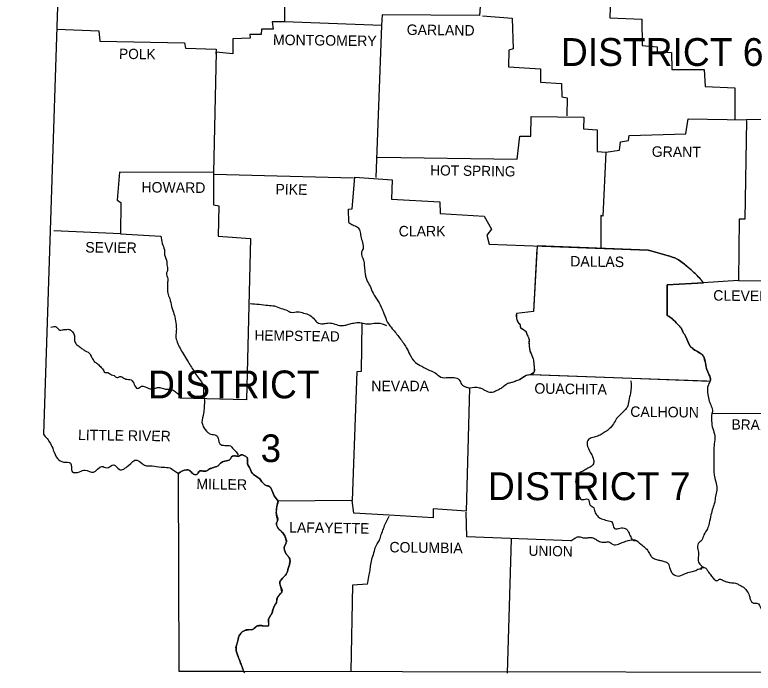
# Model space of a CAD drawing. Extents: x -17668 to 16999, y -17303 to 5867.
# Drawn here: x 1332 to 2998, y -10105 to -8621 of the extents above; entities that cross this region are included whole.
import ezdxf

# ---------------------------------------------------------------- set-up
doc = ezdxf.new("R2010")
doc.units = 0
for name, color, linetype in [('1', 7, 'Continuous'), ('2', 7, 'Continuous'), ('3', 7, 'Continuous'), ('45', 7, 'Continuous')]:
    doc.layers.add(name, color=color, linetype=linetype)

msp = doc.modelspace()

# ---------------------------------------------------------------- linework, layer by layer
at = {"layer": '1'}
for points in [[(1332.2, -7158.5), (1446.1, -8073.2), (1396.6, -9566.3)], [(1941.4, -8314.8), (1940.3, -8636.8), (1912.8, -8637.3), (1915, -8653.9), (1888.6, -8653.3), (1888, -8665.4), (1862.2, -8665.4), (1862.7, -8674.2), (1824.2, -8675.3), (1823.6, -8708.9), (1786.2, -8705.6), (1780.2, -8976.4), (1568.3, -8975.8), (1563.3, -9038.6), (1571, -9044.1), (1570.5, -9114.5), (1420.2, -9107.9)], [(2565.5, -8557), (2385.5, -8551.5), (2380.6, -8622.5), (2160.4, -8621.4), (2159.3, -8645.1)], [(2614.5, -8555.3), (2676.1, -8559.2), (2673.9, -8628), (2746, -8630.7), (2747.1, -8690.7), (2781.2, -8693.5), (2781.2, -8703.9), (2813.2, -8706.1), (2814.3, -8744.7), (2886.9, -8744.7), (2889.1, -8782.6), (2956.3, -8785.9), (2955.7, -8857.5)], [(2387.2, -8623.6), (2453.8, -8628.5), (2456, -8697.9), (2446.6, -8701.2), (2445.5, -8738.1), (2517.6, -8743), (2517.6, -8773.3), (2565.5, -8776), (2566.1, -8806.3), (2577.6, -8808), (2577.1, -8848.7)], [(2159.3, -8645.1), (1940.3, -8636.8)], [(1426.8, -8653.9), (1522, -8657.2), (1524.2, -8680.3), (1714.7, -8684.1), (1716.9, -8696.2), (1786.2, -8698.4), (1785.7, -8708.9)], [(2159.3, -8645.1), (2146.7, -8987.9)], [(3612.3, -8794.2), (3404.2, -8788.7), (3403.1, -8856.4), (2982.1, -8858)], [(2150.5, -8942.2), (2465.3, -8946.6), (2471.4, -8894.4), (2496.2, -8894.4), (2496.7, -8850.3), (2615.6, -8852), (2614.5, -8878.4), (2645.3, -8880.6), (2645.3, -8929), (2665.1, -8930.7)], [(2665.1, -8930.7), (2695.9, -8926.3), (2698.1, -8907.6), (2716.3, -8904.3), (2717.4, -8893.3), (2845.6, -8889.4), (2850.6, -8855.8), (2982.1, -8858)], [(2982.1, -8859.1), (2978.8, -9081.5), (2966.2, -9082), (2964.5, -9220.2)], [(2665.1, -8930.7), (2658.5, -9074.9), (2653.6, -9073.2), (2654.1, -9148.1)], [(1780.2, -8976.4), (1780.2, -9049.6), (1792.3, -9051.8), (1791.2, -9120), (1863.8, -9125.5), (1855, -9489.3), (1705.3, -9485.4)], [(1781.3, -8980.2), (2096.1, -8988.5)], [(2085.6, -9089.2), (2084.5, -9058.9), (2093.3, -9058.4), (2098.8, -8987.4), (2183.6, -8992.9), (2181.4, -9036.4), (2290.9, -9042.4), (2291.4, -9068.8), (2390.5, -9074.9), (2407.6, -9104.6), (2397.1, -9117.8), (2402.1, -9138.2), (2760.9, -9151.4)], [(1570.5, -9114.5), (1661.8, -9120)], [(2509.9, -9148.6), (2501.7, -9290.1), (2463.7, -9294.5)], [(2885.3, -9225.1), (2803.8, -9230.1), (2803.3, -9298.9)], [(2964.5, -9220.2), (2884.2, -9225.1)], [(2964.5, -9220.2), (3159.3, -9221.3)], [(2114.8, -9315.4), (2113.7, -9424.9), (2103.8, -9426), (2092.8, -9716)], [(2496.2, -9431.5), (2724, -9439.8), (2893, -9446.4)], [(2357.5, -9462.3), (2350.3, -9739.7), (2276, -9734.8), (2275.5, -9755.1), (2176.4, -9749.1)], [(2904, -9519.6), (3152.7, -9519)], [(1700.9, -9655), (1702, -10100.2), (3719, -10103.5)], [(2176.4, -9749.1), (2096.6, -9744.7), (2092.8, -9716), (1926, -9717.7)], [(2586.4, -9806.9), (2351.4, -9798), (2350.3, -9742.5)], [(2451.6, -9803), (2442.8, -10105.1)], [(2128, -9904.8), (2093.9, -9907), (2090, -10100.7)]]:
    msp.add_lwpolyline(points, dxfattribs=at)
for points in [[(2085.6, -9089.2), (2094.4, -9094.7), (2104.9, -9099.6), (2110.4, -9107.9), (2112.6, -9120.6), (2116.4, -9134.3), (2117.5, -9148.6), (2114.2, -9156.3), (2118.6, -9173.9), (2120.3, -9186.1), (2121.9, -9200.4), (2126.3, -9219.6), (2133.5, -9232.8), (2140.1, -9248.8), (2151.1, -9265.9), (2160.4, -9284.6), (2164.8, -9294.5), (2173.1, -9314.8), (2183.6, -9328.6), (2200.1, -9349.5), (2214.9, -9371), (2223.2, -9386.9), (2235.8, -9404.5), (2250.2, -9413.3), (2268.3, -9422.7), (2279.9, -9428.2), (2293.1, -9437.6), (2310.1, -9438.7), (2322.8, -9438.7), (2334.4, -9443.6), (2339.9, -9453.5), (2349.8, -9460.1), (2357.5, -9462.3)], [(1661.8, -9120), (1664.6, -9136.5), (1669.5, -9150.8), (1670.1, -9161.8), (1675, -9178.3), (1675, -9184.4), (1676.7, -9196.5), (1674.5, -9203.1), (1677.2, -9216.3), (1676.7, -9226.2), (1676.7, -9234.5), (1677.2, -9248.2), (1681.6, -9260.3), (1686, -9278.5), (1688.8, -9287.9), (1693.2, -9302.2), (1695.9, -9319.8), (1696.5, -9333), (1695.4, -9345.1), (1698.7, -9358.9), (1704.8, -9372.6), (1712.5, -9385.8), (1721.8, -9400.7), (1728.4, -9412.2), (1736.7, -9424.9), (1743.3, -9435.4), (1753.2, -9448.6), (1757.6, -9459.6), (1757.6, -9475), (1759.8, -9489.3), (1759.2, -9505.3), (1758.1, -9519.6), (1754.3, -9539.4), (1757, -9548.7), (1767.5, -9562.5), (1774.1, -9566.3), (1785.7, -9568.5), (1791.2, -9576.3), (1794.5, -9587.8), (1806, -9591.7), (1818.7, -9592.8), (1824.7, -9599.4), (1833, -9608.2), (1835.7, -9612.6)], [(2760.9, -9151.4), (2803.8, -9163.5), (2825.8, -9171.7), (2847.8, -9187.7), (2866, -9203.7), (2884.2, -9224)], [(1862.7, -9271.9), (1883.6, -9273.6), (1902.9, -9275.8), (1917.7, -9277.4), (1933.2, -9282.9), (1946.9, -9287.9), (1955.7, -9291.7), (1970.6, -9290.6), (1983.2, -9293.4), (1997.5, -9298.3), (2008, -9307.7), (2014.6, -9314.8), (2027.3, -9317.6), (2037.7, -9315.9), (2050.4, -9317), (2064.7, -9321.4), (2076.2, -9320.9), (2085.6, -9318.7), (2096.6, -9315.9), (2110.4, -9314.8), (2120.8, -9317), (2134.6, -9317.6), (2150.5, -9315.9), (2170.4, -9321.4)], [(2463.7, -9294.5), (2463.7, -9304.9), (2467.5, -9314.8), (2471.4, -9319.2), (2473, -9326.4), (2478, -9329.7), (2485.2, -9336.3), (2489, -9345.7), (2491.8, -9351.7), (2491.8, -9359.4), (2492.3, -9367.1), (2493.4, -9376.5), (2500, -9393), (2501.7, -9399.6), (2502.8, -9405.1), (2503.3, -9414.4), (2503.3, -9425.5), (2496.2, -9431.5)], [(2803.3, -9298.9), (2815.9, -9307.1), (2826.4, -9318.1), (2834.1, -9326.4), (2839, -9335.7), (2845.6, -9346.8), (2855, -9367.7), (2863.2, -9374.8), (2874.8, -9382), (2882, -9386.9), (2889.1, -9402.9), (2892.4, -9418.9), (2898.5, -9433.2), (2901.2, -9444.2), (2896.3, -9455.2), (2895.2, -9477.2), (2898.5, -9492), (2902.9, -9503.1), (2905.6, -9515.7), (2904, -9519.6)], [(1413.6, -9325.3), (1425.7, -9324.7), (1434, -9331.9), (1438.9, -9331.3), (1447.7, -9330.2), (1456, -9330.8), (1462, -9335.7), (1467, -9344.6), (1466.5, -9352.8), (1467, -9356.1), (1470.9, -9363.3), (1477.5, -9368.8), (1484.6, -9374.3), (1491.2, -9378.7), (1502.2, -9385.8), (1503.3, -9388), (1507.7, -9396.8), (1513.2, -9404), (1519.8, -9408.4), (1527, -9416.1), (1530.3, -9419.4), (1535.8, -9427.1), (1541.8, -9427.7), (1550.1, -9432.6), (1556.2, -9434.3), (1562.8, -9438.7), (1569.4, -9436.5), (1577.6, -9439.8), (1588.6, -9443.1), (1594.7, -9444.2), (1601.8, -9454.6), (1609, -9463.4), (1617.8, -9458.5), (1634.3, -9463.4), (1644.8, -9464), (1654.1, -9461.2), (1661.3, -9461.8), (1674.5, -9465.1), (1682.7, -9465.1), (1691.5, -9468.4), (1699.8, -9475), (1705.3, -9482.1), (1705.3, -9485.4)], [(2485.7, -9433.7), (2471.4, -9443.1), (2460.4, -9447.5), (2452.1, -9450.2), (2444.4, -9452.4), (2434.5, -9459), (2426.8, -9464.5), (2416.4, -9469.5), (2406.5, -9472.8), (2394.3, -9468.9), (2387.7, -9465.1), (2380.6, -9462.3), (2357.5, -9462.3)], [(2471.4, -9443.1), (2485.7, -9433.7), (2496.2, -9431.5)], [(2721.8, -9446.4), (2720.7, -9473.9), (2716.9, -9490.9), (2713, -9506.4), (2704.7, -9515.2), (2695.9, -9524), (2687.7, -9533.9), (2680.5, -9546), (2673.4, -9553.7), (2664, -9561.4), (2654.7, -9566.9), (2644.2, -9571.8), (2632.7, -9574.6), (2624.4, -9580.7), (2623.8, -9593.9), (2633.2, -9612.6), (2636.5, -9621.4), (2637.6, -9631.8), (2633.8, -9637.9), (2624.9, -9642.8), (2614.5, -9648.9), (2605.1, -9654.4), (2598.5, -9663.8), (2597.4, -9676.4), (2601.8, -9691.3), (2603.5, -9700.1), (2610.6, -9713.8), (2616.1, -9713.3), (2626, -9713.8), (2627.1, -9716.6), (2627.7, -9719.3), (2629.9, -9726.5), (2638.2, -9732.6), (2639.3, -9738.1), (2644.2, -9748.5), (2652.5, -9755.7), (2658.5, -9757.9), (2671.2, -9761.7), (2677.8, -9763.4), (2684.9, -9779.3), (2693.7, -9778.8), (2700.3, -9777.7), (2711.4, -9780.4), (2716.3, -9787), (2721.3, -9798), (2727.9, -9805.8), (2732.3, -9805.8)], [(2904, -9519.6), (2906.2, -9553.7), (2911.1, -9570.2), (2909.5, -9587.8), (2908.9, -9604.9), (2908.9, -9620.3), (2908.9, -9635.1), (2908.9, -9650.6), (2910, -9661.6), (2913.9, -9677.5), (2915.5, -9692.4), (2912.2, -9706.7), (2910.6, -9719.9), (2906.2, -9733.1), (2902.3, -9748), (2897.9, -9767.2), (2894.1, -9779.9), (2886.4, -9793.1), (2881.4, -9805.2), (2873.7, -9812.9), (2872.6, -9826.1), (2874.3, -9838.2), (2873.2, -9849.2), (2877, -9859.7), (2886.9, -9866.8)], [(1396.6, -9566.3), (1412.5, -9587.3), (1419.1, -9602.1), (1428.5, -9621.4), (1442.2, -9629.1), (1458.2, -9631.8), (1461.5, -9650.6), (1478, -9651.1), (1491.2, -9647.2), (1509.4, -9652.2), (1528.6, -9639), (1539.6, -9642.3), (1555.6, -9635.7), (1567.7, -9645.6), (1588.6, -9636.8), (1607.3, -9624.7), (1625, -9636.2), (1642, -9637.9), (1662.4, -9640.6), (1678.3, -9641.7), (1692.6, -9648.9), (1703.1, -9656.1), (1700.9, -9655)], [(1700.9, -9655), (1720.2, -9646.7), (1728.4, -9649.4), (1735.6, -9656.6), (1743.8, -9656.6), (1748.2, -9650), (1756.5, -9649.4), (1763.1, -9650), (1770.2, -9645.6), (1776.3, -9642.8), (1784.6, -9640.1), (1790.6, -9637.9), (1796.1, -9631.8), (1806, -9626.9), (1817.6, -9623), (1820.9, -9617.5), (1826.4, -9615.3), (1837.4, -9615.9), (1844.5, -9612.6), (1850.6, -9615.3), (1856.1, -9619.2), (1857.2, -9633.5), (1861.6, -9641.2), (1868.2, -9655), (1877.6, -9662.1), (1886.4, -9669.3), (1889.7, -9673.7), (1899, -9681.9), (1907.3, -9684.7), (1911.1, -9690.7), (1917.2, -9705), (1926, -9717.7)], [(1926, -9717.7), (1922.7, -9733.7), (1922.1, -9746.3), (1924.9, -9761.2), (1922.1, -9768.3), (1926.5, -9778.8), (1934.8, -9787), (1940.9, -9795.8), (1944.7, -9808.5), (1939.8, -9822.8), (1945.3, -9837.7), (1950.2, -9843.2), (1953, -9852), (1949.1, -9869), (1944.2, -9881.7), (1933.2, -9894.4), (1929.8, -9900.4), (1931.5, -9908.7), (1934.3, -9921.9), (1931.5, -9925.7), (1924.3, -9935.1), (1922.1, -9945.5), (1917.2, -9954.3), (1911.7, -9970.3), (1904.5, -9983.5), (1903.4, -9998.4), (1892.4, -9998.4), (1879.8, -9998.4), (1868.2, -10006.6), (1857.8, -10007.2), (1845.1, -10012.1), (1837.4, -10022.6), (1834.6, -10034.1), (1831.3, -10045.2), (1834.6, -10063.9), (1839.6, -10077.1), (1843.4, -10087.5), (1850, -10104.6)], [(2128, -9904.8), (2130.7, -9887.2), (2133.5, -9873.4), (2135.1, -9860.2), (2138.4, -9845.4), (2143.4, -9829.4), (2147.8, -9816.2), (2153.8, -9806.9), (2157.7, -9795.8), (2162.6, -9782.6), (2167.6, -9768.9), (2176.4, -9751.3)], [(2586.4, -9806.9), (2595.2, -9800.8), (2603.5, -9797.5), (2611.7, -9799.1), (2620.5, -9800.2), (2628.2, -9799.1), (2638.2, -9800.8), (2646.4, -9805.8), (2655.8, -9809.6), (2665.1, -9809.6), (2673.4, -9809.6), (2680.5, -9814.6), (2693.7, -9814), (2704.7, -9809.6), (2715.8, -9806.3), (2730.6, -9804.6), (2743.8, -9814), (2753.2, -9821.7), (2760.9, -9830.5), (2766.4, -9840.4), (2772.4, -9845.9), (2782.3, -9849.8), (2790.1, -9851.4), (2799.4, -9854.2), (2804.4, -9856.4), (2808.8, -9866.8), (2815.9, -9881.1), (2829.7, -9886.1), (2846.7, -9879.5), (2860.5, -9875.6), (2870.4, -9872.3), (2876.5, -9870.1), (2882, -9869.6), (2880.3, -9868.5), (2886.9, -9866.8), (2893, -9871.2), (2896.8, -9877.3), (2903.4, -9886.1), (2909.5, -9893.8), (2915.5, -9896.6), (2921.6, -9893.3), (2929.8, -9896), (2937, -9898.8), (2945.3, -9901), (2952.4, -9901.5), (2961.8, -9903.7), (2968.9, -9907.6), (2975.5, -9911.4), (2982.1, -9918.6), (2988.7, -9929.6), (2990.9, -9938.4), (2998.6, -9947.2), (3005.8, -9947.2), (3016.2, -9961.5), (3020.1, -9967), (3028.4, -9976.9), (3034.4, -9976.9), (3046, -9979.1)]]:
    msp.add_spline(points, degree=3, dxfattribs=at)
at = {"layer": '45'}
for points in [[(2760.9, -9151.4), (2510.3, -9142.2), (2501.7, -9290.1), (2463.7, -9294.5)], [(2803.3, -9298.9), (2803.8, -9230.1), (2885.3, -9225.1)], [(2498.8, -9431.6), (2724, -9439.8), (2900.7, -9446.7)], [(1700.9, -9655), (1702, -10100.2), (1848.4, -10100.4)]]:
    msp.add_lwpolyline(points, dxfattribs=at)
for points in [[(2885.3, -9225.1), (2866, -9203.7), (2847.8, -9187.7), (2825.8, -9171.7), (2803.8, -9163.5), (2760.9, -9151.4)], [(2463.7, -9294.5), (2463.1, -9299.7), (2463.3, -9302.3), (2463.7, -9304.9), (2464.4, -9307.5), (2465.2, -9310), (2466.3, -9312.4), (2467.5, -9314.8), (2468.4, -9316), (2469.5, -9317.1), (2470.5, -9318.1), (2471.4, -9319.2), (2471.9, -9321), (2472, -9322.9), (2472.2, -9324.8), (2472.5, -9325.7), (2473, -9326.4), (2474.2, -9327.3), (2475.5, -9328.1), (2476.8, -9328.8), (2478, -9329.7), (2479, -9330.4), (2480, -9331.2), (2481.9, -9332.7), (2483.7, -9334.3), (2484.5, -9335.3), (2485.2, -9336.3), (2486.2, -9338.6), (2487.2, -9341), (2488.1, -9343.3), (2489, -9345.7), (2490.5, -9348.6), (2491.2, -9350.1), (2491.5, -9350.9), (2491.8, -9351.7), (2492, -9353.6), (2492, -9355.5), (2491.8, -9357.5), (2491.8, -9359.4), (2491.8, -9359.8)], [(2857.9, -9370.9), (2855, -9367.7), (2854.2, -9366.5), (2853.5, -9365.2), (2852.2, -9362.6), (2850.1, -9357.3), (2848.1, -9351.9), (2845.6, -9346.8), (2842.3, -9341.3), (2839, -9335.7), (2837.8, -9333.4), (2836.8, -9330.9), (2835.6, -9328.6), (2834.1, -9326.4), (2833.1, -9325.3), (2832.2, -9324.3), (2830.3, -9322.2), (2826.4, -9318.1), (2815.9, -9307.1), (2813.1, -9304.6), (2810.1, -9302.5), (2806.8, -9300.6), (2803.3, -9298.9)], [(2491.8, -9359.8), (2492, -9363.3), (2492.3, -9367.1), (2492.7, -9371.8), (2493, -9374.1), (2493.4, -9376.5), (2494.7, -9380.7), (2496.5, -9384.8), (2498.5, -9388.8), (2500, -9393), (2501.7, -9399.6), (2502.8, -9405.1), (2503, -9407.4), (2503.1, -9409.8), (2503.3, -9414.4), (2503.4, -9417.2), (2503.5, -9420), (2503.4, -9422.7), (2503.4, -9424.1), (2503.3, -9425.5), (2502.8, -9427), (2501.8, -9428.7), (2501.1, -9429.5), (2500.4, -9430.3), (2498.8, -9431.6)], [(2900.7, -9446.7), (2901.2, -9444.2), (2900.9, -9441.4), (2900.3, -9438.7), (2898.5, -9433.2), (2897, -9429.5), (2895.4, -9426), (2893.8, -9422.5), (2892.4, -9418.9), (2891.4, -9414.9), (2890.7, -9410.9), (2890, -9406.9), (2889.1, -9402.9), (2888, -9398.6), (2886.6, -9394.3), (2884.8, -9390.4), (2882, -9386.9), (2881.1, -9386.2), (2880.2, -9385.5), (2878.5, -9384.3), (2874.8, -9382), (2863.2, -9374.8), (2858.8, -9371.6), (2857.9, -9370.9)], [(1926, -9717.7), (1917.2, -9705), (1911.1, -9690.7), (1907.3, -9684.7), (1899, -9681.9), (1889.7, -9673.7), (1886.4, -9669.3), (1877.6, -9662.1), (1868.2, -9655), (1861.6, -9641.2), (1857.2, -9633.5), (1856.1, -9619.2), (1850.6, -9615.3), (1844.5, -9612.6), (1837.4, -9615.9), (1826.4, -9615.3), (1820.9, -9617.5), (1817.6, -9623), (1806, -9626.9), (1796.1, -9631.8), (1790.6, -9637.9), (1784.6, -9640.1), (1776.3, -9642.8), (1770.2, -9645.6), (1763.1, -9650), (1756.5, -9649.4), (1748.2, -9650), (1743.8, -9656.6), (1735.6, -9656.6), (1728.4, -9649.4), (1720.2, -9646.7), (1700.9, -9655)], [(1940.1, -9825), (1939.8, -9822.8), (1940.4, -9819.2), (1942.2, -9815.7), (1944.1, -9812.1), (1944.7, -9808.5), (1944.2, -9805.4), (1943.4, -9802.2), (1942.3, -9799), (1940.9, -9795.8), (1938, -9791.2), (1934.8, -9787), (1932.8, -9785), (1930.7, -9783.1), (1928.6, -9781.1), (1926.5, -9778.8), (1923.6, -9773.6), (1922.7, -9771), (1922.1, -9768.3), (1922.5, -9766.5), (1923.5, -9764.8), (1924.5, -9763), (1924.9, -9761.2), (1924.4, -9757.5), (1923.4, -9753.8), (1922.5, -9750.1), (1922.1, -9746.3), (1922.7, -9733.7), (1923.3, -9729.3), (1924.1, -9724.8), (1926, -9717.7)], [(1928.6, -9929.4), (1931.5, -9925.7), (1932.3, -9924.8), (1933.2, -9923.9), (1934.3, -9921.9), (1934.2, -9921.1), (1934.1, -9920.2), (1933.9, -9918.6), (1933.2, -9915.3), (1932.3, -9912), (1931.5, -9908.7), (1930.5, -9904.5), (1930.1, -9902.5), (1930, -9901.4), (1929.8, -9900.4), (1933.2, -9894.4), (1935.9, -9891.1), (1938.9, -9888.1), (1941.7, -9885.1), (1943, -9883.5), (1944.2, -9881.7), (1949.1, -9869), (1951.6, -9860.5), (1952.4, -9856.2), (1953, -9852), (1950.2, -9843.2), (1949.1, -9841.7), (1947.8, -9840.4), (1946.4, -9839.2), (1945.3, -9837.7), (1941.6, -9830.3), (1940.5, -9826.5), (1940.1, -9825)], [(1865.8, -10007), (1868.2, -10006.6), (1871.2, -10004.9), (1873.9, -10002.1), (1876.6, -9999.5), (1879.8, -9998.4), (1892.4, -9998.4), (1903.4, -9998.4), (1904.8, -9997.9), (1905.4, -9996.7), (1905.1, -9992.6), (1904.2, -9987.7), (1904.5, -9983.5), (1906.3, -9980.2), (1908.2, -9977), (1910.1, -9973.7), (1911.7, -9970.3), (1913.1, -9966.4), (1914.4, -9962.3), (1915.7, -9958.3), (1917.2, -9954.3), (1918.3, -9952.1), (1919.6, -9949.9), (1921, -9947.8), (1922.1, -9945.5), (1922.8, -9943), (1923, -9940.2), (1923.3, -9937.5), (1924.3, -9935.1), (1927.9, -9930.4), (1928.6, -9929.4)], [(1848.4, -10100.4), (1843.4, -10087.5), (1839.6, -10077.1), (1834.6, -10063.9), (1833, -10059.3), (1831.7, -10054.6), (1831.1, -10049.8), (1831.3, -10045.2), (1832.9, -10039.6), (1833.8, -10036.9), (1834.6, -10034.1), (1835.4, -10031.3), (1836, -10028.4), (1836.7, -10025.5), (1837.4, -10022.6), (1840.3, -10016.8), (1842.5, -10014.4), (1845.1, -10012.1), (1851.3, -10008.9), (1857.8, -10007.2), (1860.4, -10006.9), (1863, -10006.9), (1865.7, -10007), (1865.8, -10007)]]:
    msp.add_spline(points, degree=3, dxfattribs=at)

# ---------------------------------------------------------------- texts
at = {"layer": '2'}
for s, height, rotation, p in [('GARLAND', 23.67, 359.3658, (2216, -8666.5)), ('MONTGOMERY', 23.67, 359.2944, (1914.4, -8689.1)), ('POLK', 23.11, 359.2152, (1567.2, -8720.5)), ('GRANT', 23.67, 359.4032, (2768.6, -8941.1)), ('HOT SPRING', 23.11, 359.2216, (2268.9, -8983)), ('HOWARD', 23.67, 359.5145, (1617.8, -9021.5)), ('PIKE', 23.66, 359.0452, (1919.9, -9025.9)), ('SEVIER', 23.67, 359.4271, (1491.2, -9156.9)), ('DALLAS', 23.66, 359.2462, (2584.8, -9188.3)), ('CLEVELAND', 23.67, 359.3377, (2907.3, -9265.3)), ('HEMPSTEAD', 23.11, 359.1885, (1872.6, -9355)), ('OUACHITA', 23.67, 359.2043, (2503.9, -9475)), ('CALHOUN', 23.67, 359.3634, (2720.2, -9527.3)), ('BRADLEY', 23.11, 359.1449, (2948.6, -9555.9)), ('LITTLE RIVER', 23.666, 359.1697, (1474.7, -9579.6)), ('MILLER', 23.66, 359.1319, (1741.6, -9690.2)), ('LAFAYETTE', 23.66, 359.1839, (1950.8, -9788.1)), ('COLUMBIA', 23.66, 359.2125, (2177, -9832.7)), ('UNION', 23.11, 358.9584, (2490.7, -9840.4))]:
    msp.add_text(s, height=height, rotation=rotation, dxfattribs=at).set_placement(p)
for s, p in [('CLARK', (2198, -9120.7)), ('NEVADA', (2136.2, -9469.5))]:
    msp.add_text(s, height=23.67, dxfattribs=at).set_placement(p)
at = {"layer": '3'}
for s, height, p in [('DISTRICT 6', 62.74, (2563.9, -8736.4)), ('DISTRICT', 62.74, (1632.8, -9485.6)), ('3', 62.2, (1886.6, -9629.2)), ('DISTRICT 7', 62.74, (2399.2, -9715.1))]:
    msp.add_text(s, height=height, dxfattribs=at).set_placement(p)

doc.saveas('drawing.dxf')
